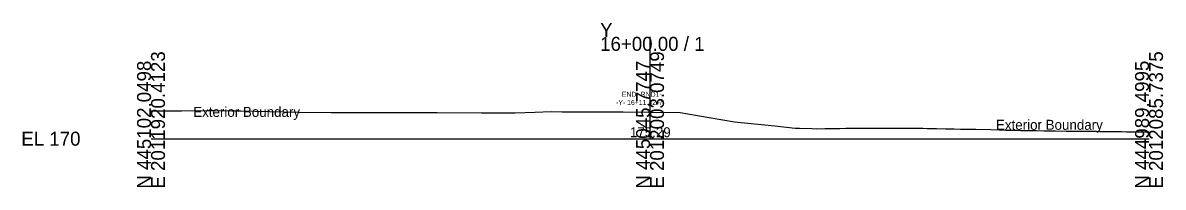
# Model space of a CAD drawing. Extents: x -26 to 3203, y -10 to 9532.
# Drawn here: x 974.3 to 1202.8, y -9.7 to 23.2 of the extents above; entities that cross this region are included whole.
import ezdxf

# ---------------------------------------------------------------- set-up
doc = ezdxf.new("R2010")
doc.units = 0
for name, color, linetype in [('Default', 7, 'Continuous'), ('Exist Cross Section Cell', 7, 'Continuous'), ('Exist XS Center Line Elevation Label', 7, 'Continuous'), ('Exist XS Ground Line', 7, 'Continuous'), ('Prop XS SE Text', 7, 'Continuous'), ('Scratch_Level_0', 7, 'Continuous')]:
    doc.layers.add(name, color=color, linetype=linetype)

msp = doc.modelspace()

# ---------------------------------------------------------------- linework, layer by layer
at = {"layer": 'Exist Cross Section Cell'}
for p, q in [((1100, 0), (1100, 20.37)), ((1000, 0), (1100, 0)), ((1100, 0), (1200, 0))]:
    msp.add_line(p, q, dxfattribs=at)
at = {"layer": 'Exist XS Ground Line'}
msp.add_lwpolyline([(1000, 5.57), (1003.73, 5.57), (1006.11, 5.6), (1011.16, 5.63), (1012.83, 5.63), (1016.22, 5.57), (1018, 5.54), (1029.48, 5.28), (1036.07, 5.25), (1040.79, 5.27), (1044.99, 5.25), (1050.3, 5.25), (1057.37, 5.23), (1066.23, 5.15), (1070.28, 5.16), (1072.97, 5.18), (1076.93, 5.29), (1080.17, 5.42), (1082.38, 5.4), (1087.37, 5.39), (1094.6, 5.35), (1100, 5.29), (1106.02, 5.21), (1107.56, 4.95), (1116.95, 3.35), (1125, 2.6), (1129.1, 2.13), (1129.98, 2.1), (1132.52, 2.02), (1133.3, 2), (1135.01, 2.03), (1136.79, 2.05), (1137.52, 2.06), (1138.04, 2.06), (1139.26, 2.08), (1141.09, 2.09), (1141.45, 2.09), (1144.21, 2.09), (1144.7, 2.09), (1145.52, 2.1), (1147.08, 2.11), (1150.28, 2.12), (1153.15, 2.11), (1153.69, 2.1), (1154.66, 2.08), (1155.57, 2.06), (1156.16, 2.05), (1157.39, 2.02), (1159.23, 1.97), (1160.92, 1.95), (1162.2, 1.93), (1162.72, 1.92), (1163.51, 1.91), (1164.58, 1.89), (1165.28, 1.88), (1168.28, 1.82), (1169.99, 1.76), (1171.35, 1.72), (1172.42, 1.7), (1173.52, 1.68), (1174.31, 1.67), (1176.8, 1.61), (1177.36, 1.61), (1178.94, 1.59), (1180.39, 1.58), (1181.26, 1.57), (1183.42, 1.53), (1185.67, 1.49), (1186.46, 1.49), (1188.08, 1.48), (1189.45, 1.48), (1190.13, 1.47), (1192.47, 1.44), (1193.33, 1.44), (1194.57, 1.42), (1195.51, 1.4), (1196.93, 1.39), (1199.03, 1.36), (1200, 1.34)], dxfattribs=at)

# ---------------------------------------------------------------- texts
at = {"layer": 'Default'}
msp.add_text('-', height=0.0001, dxfattribs=at).set_placement((1000, 0))
at = {"layer": 'Exist Cross Section Cell'}
for s, p in [('Y', (1090, 20.37)), ('16+00.00 / 1', (1090, 17.57)), ('EL 170', (974, -1.4))]:
    msp.add_text(s, height=2.8, dxfattribs=at).set_placement(p)
for s, p in [('E 2011920.4123', (1002.8, -10)), ('E 2012003.0749', (1102.8, -10)), ('E 2012085.7375', (1202.8, -10)), ('N 445102.0498', (1000, -10)), ('N 445045.7747', (1100, -10)), ('N 444989.4995', (1200, -10))]:
    msp.add_text(s, height=2.8, rotation=90, dxfattribs=at).set_placement(p)
at = {"layer": 'Exist XS Center Line Elevation Label'}
msp.add_text('175.29', height=2, dxfattribs=at).set_placement((1095.97, 0.29))
at = {"layer": 'Prop XS SE Text'}
for s, p in [('END -RND1-', (1094.36, 8.38)), ('-Y- 16+11.42+/-', (1093.19, 6.76))]:
    msp.add_text(s, height=1, dxfattribs=at).set_placement(p)
at = {"layer": 'Scratch_Level_0'}
for p in [(1008.46, 4.36), (1169.33, 1.78)]:
    msp.add_text('Exterior Boundary', height=2, dxfattribs=at).set_placement(p)

doc.saveas('drawing.dxf')
